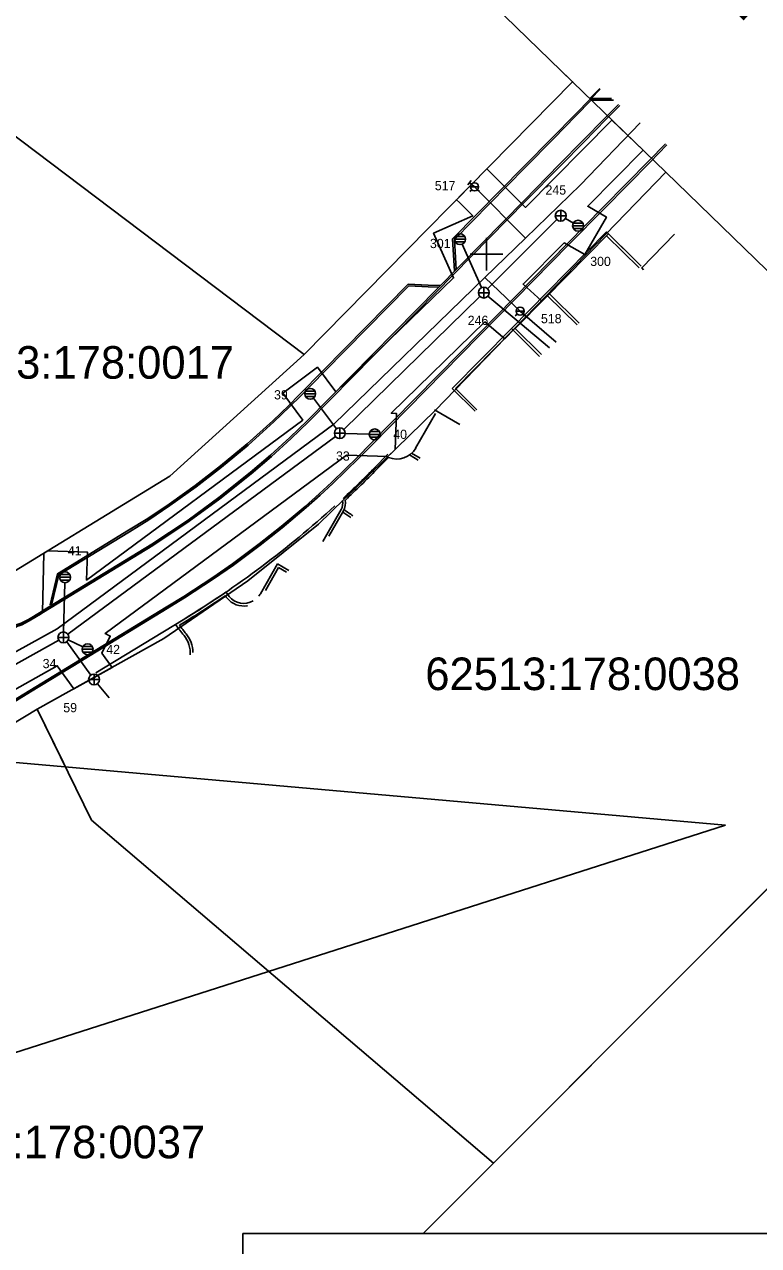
# Model space of a CAD drawing. Extents: x 531722 to 532110, y 6469397 to 6469678.
# Drawn here: x 531907.4 to 531975.1, y 6469508.7 to 6469621.2 of the extents above; entities that cross this region are included whole.
import ezdxf

# ---------------------------------------------------------------- set-up
doc = ezdxf.new("R2010")
doc.units = 0
for name, color, linetype in [('ABIJOONIS', 7, 'Continuous'), ('Default', 7, 'Continuous'), ('HOONE', 7, 'Continuous'), ('IKÕ alad', 7, 'Continuous'), ('KAEVUNR_SKKAEV', 7, 'Continuous'), ('KAEVUNR_VKAEV', 7, 'Continuous'), ('PIIR', 7, 'Continuous'), ('PIIRIMLEITUD', 7, 'Continuous'), ('SKKAEV', 7, 'Continuous'), ('SKTRASS', 7, 'Continuous'), ('TEE', 7, 'Continuous'), ('VKAEV', 7, 'Continuous'), ('VORK', 7, 'Continuous'), ('VORMISTUS', 7, 'Continuous'), ('VTRASS', 7, 'Continuous')]:
    doc.layers.add(name, color=color, linetype=linetype)

msp = doc.modelspace()

# ---------------------------------------------------------------- linework, layer by layer
at = {"layer": 'Default'}
for q in [(531897.12, 6469554), (531869.45, 6469514.57)]:
    msp.add_line((531972.02, 6469547.42), q, dxfattribs=at)
at = {"layer": 'HOONE'}
msp.add_lwpolyline([(531967.31, 6469601.84), (531964.31, 6469598.74), (531964.48, 6469598.58)], dxfattribs=at)
at = {"layer": 'IKÕ alad'}
msp.add_lwpolyline([(531902.38, 6469563.34), (531909.07, 6469567.01), (531909.22, 6469572.46), (531909.56, 6469572.67), (531913.22, 6469572.57), (531913.15, 6469569.98), (531933.07, 6469584.73), (531931.22, 6469587.19), (531934.42, 6469589.6), (531936.12, 6469587.33), (531946.96, 6469597.83), (531945.13, 6469601.93), (531948.74, 6469603.54), (531947.52, 6469604.76), (531947.23, 6469605.03), (531950.04, 6469607.88), (531950.23, 6469607.69), (531953.59, 6469604.32), (531961.56, 6469612.34), (531964.45, 6469609.58), (531959.33, 6469604.42), (531961.05, 6469603.43), (531959.05, 6469599.97), (531957.17, 6469601.05), (531953.37, 6469597.26), (531955.06, 6469595.7), (531951.7, 6469592.22), (531949.85, 6469593.77), (531941.22, 6469585.35), (531941.61, 6469585.34), (531941.7, 6469585.34), (531941.58, 6469582.01), (531940.91, 6469581.36), (531937.11, 6469581.5), (531914.85, 6469565.05), (531915.32, 6469564.82), (531914.55, 6469563.24), (531915.41, 6469562.05), (531915.5, 6469561.94), (531911.98, 6469559.97), (531910.44, 6469562.09), (531902.27, 6469557.52)], dxfattribs=at)
at = {"layer": 'PIIR'}
for points in [[(531956.63, 6469617.16), (531957.93, 6469615.9), (531933.2, 6469590.77), (531905.81, 6469611.45), (531898.93, 6469616.64), (531894.32, 6469620.12)], [(531969.64, 6469604.54), (531966.54, 6469607.55), (531957.93, 6469615.9), (531956.63, 6469617.16)], [(531903.32, 6469568.86), (531920.82, 6469579.55), (531933.2, 6469590.77), (531957.93, 6469615.9), (531966.54, 6469607.55), (531945.28, 6469585.6), (531934.51, 6469575.15), (531928, 6469569.93), (531920.25, 6469564.6), (531908.6, 6469558.08), (531892, 6469548.07)], [(531911.02, 6469553.14), (531908.6, 6469558.08), (531920.25, 6469564.6), (531928, 6469569.93), (531934.51, 6469575.15), (531945.28, 6469585.6), (531966.54, 6469607.55), (531969.64, 6469604.54)], [(531869.08, 6469519.75), (531868.96, 6469525.97), (531878.09, 6469535.46), (531892, 6469548.07), (531908.6, 6469558.08), (531911.02, 6469553.14)]]:
    msp.add_lwpolyline(points, dxfattribs=at)
msp.add_lwpolyline([(531905.81, 6469611.45), (531933.2, 6469590.77), (531920.82, 6469579.55), (531903.32, 6469568.86), (531892.32, 6469591.31)], close=True, dxfattribs=at)
at = {"layer": 'PIIRIMLEITUD'}
for points in [[(532067.33, 6469509.78), (532004.76, 6469570.47), (531966.54, 6469607.55), (531957.93, 6469615.9), (531899.65, 6469672.42), (531893.61, 6469678.27)], [(531903.32, 6469568.86), (531920.82, 6469579.55), (531933.2, 6469590.77), (531957.93, 6469615.9), (531966.54, 6469607.55), (531945.28, 6469585.6), (531934.51, 6469575.15), (531928, 6469569.93), (531920.25, 6469564.6), (531908.6, 6469558.08), (531892, 6469548.07)], [(531927.55, 6469493.15), (531911.54, 6469477.11), (531890.48, 6469498.54), (531869.08, 6469519.62), (531868.96, 6469525.97), (531878.09, 6469535.46), (531892, 6469548.07), (531908.6, 6469558.08), (531913.6, 6469547.88), (531950.63, 6469516.26), (531944.16, 6469509.78)], [(531944.16, 6469509.78), (531950.63, 6469516.26), (531978.55, 6469544.22), (532013.37, 6469509.78)]]:
    msp.add_lwpolyline(points, dxfattribs=at)
for points in [[(531899.65, 6469672.42), (531957.93, 6469615.9), (531933.2, 6469590.77), (531905.81, 6469611.45), (531898.93, 6469616.64), (531861.91, 6469644.6), (531880.45, 6469659.84)], [(531905.81, 6469611.45), (531933.2, 6469590.77), (531920.82, 6469579.55), (531903.32, 6469568.86), (531892.32, 6469591.31)], [(531966.54, 6469607.55), (532004.76, 6469570.47), (531950.63, 6469516.26), (531913.6, 6469547.88), (531908.6, 6469558.08), (531920.25, 6469564.6), (531928, 6469569.93), (531934.51, 6469575.15), (531945.28, 6469585.6)]]:
    msp.add_lwpolyline(points, close=True, dxfattribs=at)
at = {"layer": 'SKKAEV'}
for p, q in [((531957.34, 6469603.54), (531956.34, 6469603.54)), ((531956.84, 6469604.05), (531956.84, 6469603.05)), ((531957.94, 6469602.63), (531958.94, 6469602.63)), ((531958.01, 6469602.88), (531958.88, 6469602.88)), ((531958.01, 6469602.38), (531958.88, 6469602.38)), ((531947.06, 6469601.39), (531948.06, 6469601.39)), ((531947.13, 6469601.64), (531947.99, 6469601.64)), ((531947.13, 6469601.14), (531947.99, 6469601.14)), ((531950.25, 6469596.46), (531949.25, 6469596.46)), ((531949.75, 6469596.97), (531949.75, 6469595.97)), ((531933.25, 6469587.15), (531934.25, 6469587.15)), ((531933.32, 6469587.4), (531934.19, 6469587.4)), ((531933.32, 6469586.9), (531934.19, 6469586.9)), ((531936.98, 6469583.51), (531935.98, 6469583.51)), ((531936.48, 6469584.02), (531936.48, 6469583.02)), ((531939.2, 6469583.41), (531940.2, 6469583.41)), ((531939.27, 6469583.66), (531940.13, 6469583.66)), ((531939.27, 6469583.16), (531940.13, 6469583.16)), ((531910.66, 6469570.24), (531911.66, 6469570.24)), ((531910.73, 6469570.49), (531911.59, 6469570.49)), ((531910.73, 6469569.99), (531911.59, 6469569.99)), ((531911.01, 6469565.21), (531911.01, 6469564.21)), ((531911.51, 6469564.7), (531910.51, 6469564.7)), ((531912.81, 6469563.86), (531913.67, 6469563.86)), ((531912.74, 6469563.61), (531913.74, 6469563.61)), ((531912.81, 6469563.36), (531913.67, 6469563.36)), ((531914.33, 6469560.82), (531913.33, 6469560.82)), ((531913.83, 6469561.33), (531913.83, 6469560.33))]:
    msp.add_line(p, q, dxfattribs=at)
for centre in [(531956.84, 6469603.55), (531958.44, 6469602.63), (531947.56, 6469601.39), (531949.75, 6469596.47), (531933.75, 6469587.15), (531936.48, 6469583.52), (531939.7, 6469583.41), (531911.16, 6469570.24), (531911.01, 6469564.71), (531913.24, 6469563.61), (531913.83, 6469560.83)]:
    msp.add_circle(centre, 0.5, dxfattribs=at)
at = {"layer": 'SKTRASS'}
for points in [[(531950.1, 6469596.82), (531956.49, 6469603.2)], [(531957.27, 6469603.3), (531958.01, 6469602.88)], [(531947.77, 6469600.93), (531949.55, 6469596.93)], [(531936.84, 6469583.87), (531949.39, 6469596.12)], [(531950.13, 6469596.15), (531953.09, 6469593.66), (531955.81, 6469591.38)], [(531934.05, 6469586.75), (531936.18, 6469583.92)], [(531911.42, 6469565), (531936.08, 6469583.22)], [(531936.98, 6469583.5), (531939.2, 6469583.42)], [(531911.03, 6469565.2), (531911.15, 6469569.74)], [(531901.66, 6469559.47), (531910.58, 6469564.46)], [(531911.31, 6469564.3), (531913.54, 6469561.23)], [(531911.46, 6469564.48), (531912.79, 6469563.83)], [(531914.15, 6469560.44), (531915.22, 6469559.14)]]:
    msp.add_lwpolyline(points, dxfattribs=at)
at = {"layer": 'TEE'}
for p, q in [((531955.45, 6469596), (531961.23, 6469601.88)), ((531955.62, 6469596.54), (531961.05, 6469602.06)), ((531964.25, 6469598.92), (531961.05, 6469602.06)), ((531964.08, 6469598.74), (531961.06, 6469601.71)), ((531964.25, 6469598.92), (531962.4, 6469600.74)), ((531952.29, 6469593.15), (531955.62, 6469596.54)), ((531952.64, 6469593.15), (531955.45, 6469596)), ((531955.62, 6469596.18), (531958.36, 6469593.49)), ((531955.8, 6469596.36), (531958.55, 6469593.65)), ((531946.85, 6469587.63), (531952.29, 6469593.15)), ((531954.89, 6469590.59), (531952.29, 6469593.15)), ((531955.08, 6469590.76), (531952.64, 6469593.15)), ((531947.13, 6469587.63), (531952.43, 6469593.01)), ((531948.97, 6469585.54), (531946.85, 6469587.63)), ((531949.12, 6469585.67), (531947.13, 6469587.63)), ((531945.29, 6469585.32), (531943.47, 6469582.14)), ((531945.2, 6469585.66), (531947.54, 6469584.32)), ((531939.68, 6469580.34), (531940.92, 6469581.59)), ((531939.86, 6469580.16), (531940.97, 6469581.29)), ((531940.71, 6469581.38), (531940.74, 6469581.41)), ((531943.7, 6469581.04), (531942.89, 6469581.51)), ((531943.1, 6469581.68), (531943.9, 6469581.22)), ((531936.6, 6469576.48), (531934.91, 6469573.54)), ((531936.81, 6469576.36), (531935.48, 6469574.02)), ((531930.73, 6469571.47), (531929.16, 6469568.72)), ((531930.83, 6469571.13), (531929.62, 6469569.02)), ((531931.79, 6469570.87), (531930.73, 6469571.47)), ((531931.58, 6469570.7), (531930.83, 6469571.13)), ((531927.95, 6469567.6), (531927.92, 6469567.61)), ((531922.05, 6469566.33), (531914.01, 6469561.43)), ((531922.05, 6469566.33), (531921.33, 6469565.89)), ((531922.18, 6469566.12), (531921.7, 6469565.82))]:
    msp.add_line(p, q, dxfattribs=at)
for points in [[(531959.56, 6469614.38), (531960.43, 6469615.27)], [(531959.62, 6469614.32), (531960.49, 6469615.21)], [(531962.16, 6469613.81), (531960.93, 6469612.56), (531958.88, 6469610.48), (531956.71, 6469608.27), (531953.5, 6469605), (531943.54, 6469594.88), (531933.48, 6469584.67), (531931.89, 6469583.13), (531930.08, 6469581.49), (531928.22, 6469579.89), (531925.33, 6469577.58), (531922.5, 6469575.52), (531919.17, 6469573.31), (531909.08, 6469567.14)], [(531962.28, 6469613.72), (531961.04, 6469612.46), (531958.99, 6469610.37), (531956.81, 6469608.16), (531953.6, 6469604.9), (531943.65, 6469594.77), (531933.59, 6469584.56), (531931.99, 6469583.02), (531930.18, 6469581.38), (531928.32, 6469579.77), (531925.42, 6469577.46), (531922.59, 6469575.4), (531919.25, 6469573.18), (531909.18, 6469567.03)], [(531961.51, 6469614.36), (531960.46, 6469614.35), (531959.6, 6469614.34), (531958.13, 6469612.86), (531956.07, 6469610.75), (531953.45, 6469608.09), (531946.88, 6469601.42), (531947.05, 6469598.45)], [(531961.69, 6469614.21), (531960.46, 6469614.2), (531959.66, 6469614.19), (531958.24, 6469612.75), (531956.17, 6469610.65), (531953.55, 6469607.99), (531947.04, 6469601.36), (531947.19, 6469598.59)], [(531966.5, 6469610.16), (531964.96, 6469608.6), (531962.91, 6469606.52), (531960.73, 6469604.3), (531957.52, 6469601.04), (531947.57, 6469590.92), (531939.32, 6469582.53), (531938.14, 6469581.33), (531935.73, 6469578.99), (531934.57, 6469577.93), (531933.28, 6469576.77), (531931.08, 6469574.92), (531929.06, 6469573.32), (531926.59, 6469571.49), (531924.77, 6469570.22), (531922.1, 6469568.48), (531920.49, 6469567.49), (531912.82, 6469562.81)], [(531966.61, 6469610.07), (531965.07, 6469608.5), (531963.02, 6469606.41), (531960.84, 6469604.2), (531957.63, 6469600.94), (531947.67, 6469590.81), (531939.43, 6469582.43), (531938.24, 6469581.23), (531935.83, 6469578.88), (531934.67, 6469577.81), (531933.37, 6469576.66), (531931.17, 6469574.8), (531929.15, 6469573.21), (531926.68, 6469571.37), (531924.85, 6469570.1), (531922.18, 6469568.35), (531920.56, 6469567.37), (531912.92, 6469562.7)], [(531945.74, 6469597.12), (531944.62, 6469597.16), (531942.77, 6469597.24), (531934.96, 6469589.29), (531932.75, 6469587.05), (531931.78, 6469586.08), (531930.3, 6469584.66), (531927.94, 6469582.54), (531925.5, 6469580.5), (531923.16, 6469578.71), (531920.75, 6469576.98), (531918.78, 6469575.67), (531917.02, 6469574.57), (531910.47, 6469570.57), (531909.78, 6469567.7)], [(531945.6, 6469596.98), (531944.61, 6469597.01), (531942.83, 6469597.08), (531935.06, 6469589.19), (531932.85, 6469586.94), (531931.88, 6469585.97), (531930.4, 6469584.55), (531928.04, 6469582.43), (531925.59, 6469580.39), (531923.25, 6469578.59), (531920.83, 6469576.86), (531918.87, 6469575.55), (531917.1, 6469574.44), (531910.6, 6469570.48), (531909.92, 6469567.66)], [(531909.08, 6469567.14), (531908.81, 6469566.98), (531907.79, 6469566.36), (531907.11, 6469566.01), (531906.46, 6469565.8), (531905.95, 6469565.7), (531905.43, 6469565.65), (531904.51, 6469565.7), (531903.79, 6469565.87), (531903.51, 6469565.97), (531903.1, 6469566.15), (531902.7, 6469566.38), (531902.05, 6469566.86), (531901.6, 6469567.31), (531901.26, 6469567.75), (531900.93, 6469568.33)], [(531909.18, 6469567.03), (531908.91, 6469566.86), (531907.86, 6469566.23), (531907.17, 6469565.87), (531906.5, 6469565.65), (531905.97, 6469565.55), (531905.43, 6469565.5), (531904.49, 6469565.56), (531903.46, 6469565.83), (531902.62, 6469566.25), (531901.95, 6469566.74), (531901.49, 6469567.21), (531901.14, 6469567.67), (531900.8, 6469568.25)], [(531912.82, 6469562.81), (531912.49, 6469562.61), (531907.91, 6469559.81), (531901.1, 6469555.66), (531899.11, 6469554.44)], [(531912.92, 6469562.7), (531912.59, 6469562.5), (531907.98, 6469559.68), (531901.18, 6469555.53), (531899.19, 6469554.31)]]:
    msp.add_lwpolyline(points, dxfattribs=at)
for centre, radius, start, end in [((531941.74, 6469583.14), 2, 247.4894, 330.1872), ((531874.36, 6469644.47), 91.55, 312.9971, 315.5236), ((531874.34, 6469644.5), 91.83, 313.0206, 315.5236), ((531935.51, 6469577.1), 1.5, 330.1873, 9.9764), ((531874.39, 6469644.44), 91.5, 301.3904, 312.3457), ((531935.51, 6469577.1), 1.25, 330.1873, 9.9764), ((531949.23, 6469593.15), 21, 233.5721, 236.0125), ((531949.23, 6469593.15), 20.75, 233.4752, 236.2044), ((531874.39, 6469644.44), 91.5, 301.3904, 304.316), ((531874.39, 6469644.44), 91.75, 301.3904, 304.1689), ((531937.32, 6469577.5), 14.5, 218.2191, 219.2605), ((531937.32, 6469577.5), 14.25, 217.2819, 219.2605), ((531927.64, 6469569.59), 2, 219.2605, 279.7062), ((531927.64, 6469569.59), 1.75, 219.2605, 299.5608), ((531927.64, 6469569.59), 1.75, 321.411, 330.1873), ((531937.32, 6469577.5), 19.75, 215.9846, 219.7146), ((531937.32, 6469577.5), 19.5, 216.781, 219.7146), ((531920.24, 6469563.31), 2.7, 0.0893, 39.7146), ((531920.24, 6469563.31), 2.45, 354.9078, 39.7146)]:
    msp.add_arc(centre, radius, start, end, dxfattribs=at)
at = {"layer": 'VKAEV'}
for p, q in [((531948.64, 6469605.95), (531948.46, 6469605.77)), ((531948.53, 6469606.21), (531949.28, 6469606.21)), ((531949.17, 6469605.95), (531949.34, 6469605.77)), ((531952.83, 6469594.49), (531952.65, 6469594.32)), ((531952.72, 6469594.76), (531953.47, 6469594.76)), ((531953.36, 6469594.49), (531953.54, 6469594.32))]:
    msp.add_line(p, q, dxfattribs=at)
for centre in [(531948.9, 6469606.21), (531953.1, 6469594.76)]:
    msp.add_circle(centre, 0.375, dxfattribs=at)
at = {"layer": 'VORK'}
for p, q in [((531950, 6469601.5), (531950, 6469598.5)), ((531948.5, 6469600), (531951.5, 6469600))]:
    msp.add_line(p, q, dxfattribs=at)
at = {"layer": 'VORMISTUS'}
msp.add_lwpolyline([(531722.31, 6469396.91), (531927.55, 6469396.91), (531927.55, 6469509.78), (532109.74, 6469509.78), (532109.74, 6469678.27), (531722.31, 6469678.27), (531722.31, 6469396.91)], dxfattribs=at)
at = {"layer": 'VTRASS'}
msp.add_line((531948.28, 6469606.41), (531948.6, 6469606.79), dxfattribs=at)
for points in [[(531864.06, 6469528.19), (531865, 6469530.17), (531866.78, 6469531.96), (531881.43, 6469546.7), (531896.89, 6469557.43), (531901.12, 6469560.37), (531910.44, 6469565.48), (531935.93, 6469584.36), (531949.85, 6469597.85), (531953.59, 6469601.48), (531958.66, 6469606.39), (531964.17, 6469612.12)], [(531948.44, 6469606.6), (531948.9, 6469606.21), (531953.59, 6469601.48)], [(531949.85, 6469597.85), (531953.1, 6469594.76), (531956.41, 6469591.89)]]:
    msp.add_lwpolyline(points, dxfattribs=at)

# ---------------------------------------------------------------- texts
at = {"layer": 'ABIJOONIS'}
msp.add_text('Mai tn', height=5.851, rotation=316.0369, dxfattribs=at).set_placement((531965, 6469629.93))
for s, p in [('62513:178:0017', (531897.73, 6469588.54)), ('62513:178:0038', (531944.36, 6469559.85)), ('62513:178:0037', (531895.08, 6469516.72))]:
    msp.add_text(s, height=3, dxfattribs=at).set_placement(p)
at = {"layer": 'KAEVUNR_SKKAEV'}
for s, p in [('245', (531955.44, 6469605.5)), ('301', (531944.79, 6469600.57)), ('300', (531959.56, 6469598.92)), ('246', (531948.27, 6469593.49)), ('39', (531930.42, 6469586.63)), ('40', (531941.41, 6469582.99)), ('33', (531936.13, 6469580.99)), ('41', (531911.42, 6469572.26)), ('42', (531914.96, 6469563.17)), ('34', (531909.1, 6469561.87)), ('59', (531911, 6469557.81))]:
    msp.add_text(s, height=0.85, dxfattribs=at).set_placement(p)
at = {"layer": 'KAEVUNR_VKAEV'}
for s, p in [('517', (531945.24, 6469605.9)), ('518', (531955.02, 6469593.65))]:
    msp.add_text(s, height=0.85, dxfattribs=at).set_placement(p)

doc.saveas('drawing.dxf')
